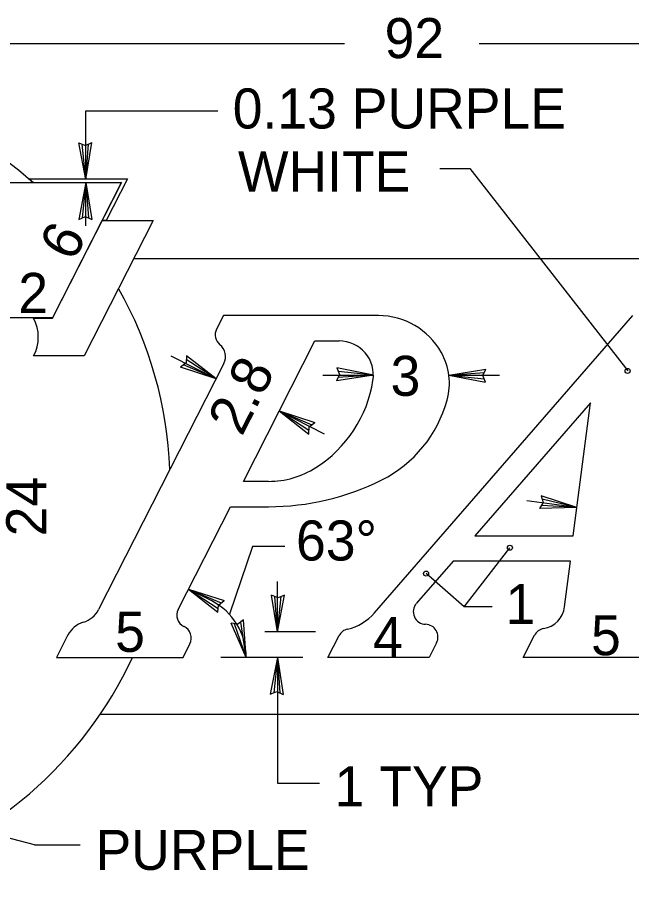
# Model space of a CAD drawing. Extents: x 10268197 to 10269179, y 2141503 to 2142677.
# Drawn here: x 10268485.36 to 10268496.1, y 2142121.42 to 2142136.69 of the extents above; entities that cross this region are included whole.
import ezdxf

# ---------------------------------------------------------------- set-up
doc = ezdxf.new("R2010")
doc.units = 0
for name, color, linetype in [('1', 7, 'Continuous'), ('3', 7, 'Continuous'), ('52', 7, 'Continuous'), ('SOILS_SP83_SHP', 7, 'Continuous')]:
    doc.layers.add(name, color=color, linetype=linetype)

msp = doc.modelspace()

# ---------------------------------------------------------------- linework, layer by layer
at = {"layer": '1'}
for p, q in [((10268467.878, 2142136.24), (10268491.08, 2142136.24)), ((10268493.435, 2142136.24), (10268512.635, 2142136.24)), ((10268486.559, 2142135.062), (10268488.866, 2142135.062)), ((10268486.559, 2142133.891), (10268486.559, 2142135.062)), ((10268492.748, 2142134.055), (10268493.275, 2142134.055)), ((10268493.275, 2142134.055), (10268496.035, 2142130.516)), ((10268486.559, 2142133.049), (10268486.559, 2142133.812)), ((10268485.973, 2142131.438), (10268486.842, 2142133.143)), ((10268487.736, 2142133.143), (10268486.53, 2142130.777)), ((10268486.842, 2142133.143), (10268487.736, 2142133.143)), ((10268485.644, 2142131.438), (10268485.973, 2142131.438)), ((10268486.53, 2142130.777), (10268485.645, 2142130.777)), ((10268488.047, 2142130.78), (10268488.835, 2142130.378)), ((10268490.703, 2142130.444), (10268491.588, 2142130.444)), ((10268492.906, 2142130.444), (10268493.791, 2142130.444)), ((10268489.94, 2142129.816), (10268490.728, 2142129.414)), ((10268495.146, 2142128.128), (10268494.269, 2142128.243)), ((10268489.47, 2142127.445), (10268489.069, 2142126.262)), ((10268490.039, 2142127.445), (10268489.47, 2142127.445)), ((10268493.177, 2142126.394), (10268493.974, 2142127.426)), ((10268493.177, 2142126.394), (10268492.508, 2142126.973)), ((10268489.908, 2142125.953), (10268489.908, 2142126.837)), ((10268488.76, 2142126.496), (10268488.353, 2142126.703)), ((10268493.666, 2142126.394), (10268493.177, 2142126.394)), ((10268490.572, 2142125.953), (10268489.687, 2142125.953)), ((10268490.351, 2142125.51), (10268488.921, 2142125.51)), ((10268489.908, 2142125.51), (10268489.908, 2142123.311)), ((10268489.908, 2142123.311), (10268490.645, 2142123.311)), ((10268485.66, 2142122.233), (10268483.388, 2142122.827)), ((10268485.66, 2142122.233), (10268486.461, 2142122.233))]:
    msp.add_line(p, q, dxfattribs=at)
for centre in [(10268496.034, 2142130.515), (10268493.974, 2142127.425), (10268492.508, 2142126.973)]:
    msp.add_circle(centre, 0.0442, dxfattribs=at)
for centre, radius, start, end in [((10268485.019, 2142131.107), 0.708, 332.2089, 27.9127), ((10268488.257, 2142125.51), 1.106, 0, 62.9941)]:
    msp.add_arc(centre, radius, start, end, dxfattribs=at)
at = {"layer": '3'}
msp.add_lwpolyline([(10268485.563, 2142133.872), (10268487.288, 2142133.872), (10268486.916, 2142133.143), (10268486.842, 2142133.143), (10268487.18, 2142133.806), (10268485.64, 2142133.805)], close=True, dxfattribs=at)
at = {"layer": '52'}
for p, q in [((10268486.56, 2142133.86), (10268486.436, 2142134.503)), ((10268486.436, 2142134.503), (10268486.55, 2142134.456)), ((10268486.56, 2142133.86), (10268486.496, 2142134.479)), ((10268486.55, 2142134.456), (10268486.663, 2142134.507)), ((10268486.56, 2142133.86), (10268486.663, 2142134.507)), ((10268486.56, 2142133.86), (10268486.604, 2142134.48)), ((10268486.56, 2142133.808), (10268486.436, 2142133.164)), ((10268486.56, 2142133.808), (10268486.496, 2142133.189)), ((10268486.56, 2142133.808), (10268486.663, 2142133.161)), ((10268486.56, 2142133.808), (10268486.604, 2142133.188)), ((10268486.436, 2142133.164), (10268486.55, 2142133.212)), ((10268486.55, 2142133.212), (10268486.663, 2142133.161)), ((10268488.32, 2142130.781), (10268488.31, 2142130.658)), ((10268488.835, 2142130.378), (10268488.314, 2142130.716)), ((10268488.835, 2142130.378), (10268488.32, 2142130.781)), ((10268488.31, 2142130.658), (10268488.213, 2142130.58)), ((10268488.835, 2142130.378), (10268488.213, 2142130.58)), ((10268488.835, 2142130.378), (10268488.264, 2142130.621)), ((10268491.588, 2142130.444), (10268490.945, 2142130.568)), ((10268490.945, 2142130.568), (10268490.992, 2142130.454)), ((10268492.906, 2142130.444), (10268493.553, 2142130.546)), ((10268493.502, 2142130.433), (10268493.553, 2142130.546)), ((10268490.992, 2142130.454), (10268490.941, 2142130.341)), ((10268491.588, 2142130.444), (10268490.941, 2142130.341)), ((10268491.588, 2142130.444), (10268490.968, 2142130.4)), ((10268491.588, 2142130.444), (10268490.969, 2142130.508)), ((10268492.906, 2142130.444), (10268493.525, 2142130.487)), ((10268492.906, 2142130.444), (10268493.549, 2142130.319)), ((10268492.906, 2142130.444), (10268493.524, 2142130.379)), ((10268493.549, 2142130.319), (10268493.502, 2142130.433)), ((10268489.94, 2142129.816), (10268490.563, 2142129.614)), ((10268489.94, 2142129.816), (10268490.456, 2142129.413)), ((10268489.94, 2142129.816), (10268490.461, 2142129.478)), ((10268489.94, 2142129.816), (10268490.512, 2142129.574)), ((10268490.456, 2142129.413), (10268490.466, 2142129.536)), ((10268490.466, 2142129.536), (10268490.563, 2142129.614)), ((10268495.146, 2142128.128), (10268494.524, 2142128.335)), ((10268494.524, 2142128.335), (10268494.557, 2142128.215)), ((10268495.146, 2142128.128), (10268494.541, 2142128.272)), ((10268494.557, 2142128.215), (10268494.491, 2142128.11)), ((10268495.146, 2142128.128), (10268494.491, 2142128.11)), ((10268495.146, 2142128.128), (10268494.526, 2142128.165)), ((10268488.353, 2142126.703), (10268488.976, 2142126.501)), ((10268488.353, 2142126.703), (10268488.869, 2142126.3)), ((10268488.353, 2142126.703), (10268488.874, 2142126.365)), ((10268488.353, 2142126.703), (10268488.925, 2142126.46)), ((10268489.908, 2142125.953), (10268489.806, 2142126.599)), ((10268489.919, 2142126.548), (10268489.806, 2142126.599)), ((10268489.908, 2142125.953), (10268489.865, 2142126.572)), ((10268489.908, 2142125.953), (10268490.033, 2142126.596)), ((10268489.908, 2142125.953), (10268489.973, 2142126.571)), ((10268490.033, 2142126.596), (10268489.919, 2142126.548)), ((10268488.869, 2142126.3), (10268488.878, 2142126.423)), ((10268488.878, 2142126.423), (10268488.976, 2142126.501)), ((10268489.364, 2142125.51), (10268489.097, 2142126.109)), ((10268489.219, 2142126.089), (10268489.097, 2142126.109)), ((10268489.318, 2142126.164), (10268489.219, 2142126.089)), ((10268489.364, 2142125.51), (10268489.266, 2142126.124)), ((10268489.364, 2142125.51), (10268489.318, 2142126.164)), ((10268489.364, 2142125.51), (10268489.161, 2142126.097)), ((10268489.908, 2142125.51), (10268489.783, 2142124.867)), ((10268489.908, 2142125.51), (10268489.844, 2142124.892)), ((10268489.908, 2142125.51), (10268490.011, 2142124.863)), ((10268489.908, 2142125.51), (10268489.952, 2142124.891)), ((10268489.783, 2142124.867), (10268489.898, 2142124.915)), ((10268489.898, 2142124.915), (10268490.011, 2142124.863))]:
    msp.add_line(p, q, dxfattribs=at)
at = {"layer": 'SOILS_SP83_SHP'}
for p, q in [((10268479.658, 2142133.806), (10268487.18, 2142133.806)), ((10268485.563, 2142133.872), (10268487.288, 2142133.872)), ((10268487.18, 2142133.806), (10268485.975, 2142131.441)), ((10268487.288, 2142133.872), (10268486.916, 2142133.143)), ((10268485.973, 2142131.438), (10268486.842, 2142133.143)), ((10268487.736, 2142133.143), (10268486.53, 2142130.777)), ((10268486.842, 2142133.143), (10268487.736, 2142133.143)), ((10268487.397, 2142132.479), (10268512.635, 2142132.479)), ((10268488.965, 2142131.483), (10268488.845, 2142131.247)), ((10268491.675, 2142131.483), (10268488.965, 2142131.483)), ((10268491.607, 2142126.287), (10268496.125, 2142131.483)), ((10268485.975, 2142131.441), (10268485.09, 2142131.441)), ((10268485.644, 2142131.438), (10268485.973, 2142131.438)), ((10268489.313, 2142128.585), (10268490.564, 2142131.041)), ((10268490.564, 2142131.041), (10268490.991, 2142131.041)), ((10268486.53, 2142130.777), (10268485.645, 2142130.777)), ((10268488.973, 2142130.647), (10268486.782, 2142126.348)), ((10268495.384, 2142129.957), (10268493.364, 2142127.634)), ((10268495.082, 2142127.634), (10268495.384, 2142129.957)), ((10268489.751, 2142128.585), (10268489.313, 2142128.585)), ((10268488.172, 2142126.348), (10268489.087, 2142128.143)), ((10268489.087, 2142128.143), (10268489.751, 2142128.143)), ((10268493.364, 2142127.634), (10268495.082, 2142127.634)), ((10268492.981, 2142127.191), (10268492.339, 2142126.454)), ((10268495.037, 2142127.191), (10268492.981, 2142127.191)), ((10268494.932, 2142126.392), (10268495.037, 2142127.191)), ((10268486.245, 2142125.901), (10268486.046, 2142125.51)), ((10268490.793, 2142125.51), (10268490.986, 2142125.889)), ((10268494.207, 2142125.51), (10268494.403, 2142125.895)), ((10268488.258, 2142125.51), (10268488.378, 2142125.747)), ((10268492.693, 2142125.766), (10268492.563, 2142125.51)), ((10268486.046, 2142125.51), (10268488.258, 2142125.51)), ((10268492.563, 2142125.51), (10268490.793, 2142125.51)), ((10268496.419, 2142125.51), (10268494.207, 2142125.51)), ((10268486.81, 2142124.515), (10268508.578, 2142124.515))]:
    msp.add_line(p, q, dxfattribs=at)
for centre, radius, start, end in [((10268480.957, 2142128.496), 7.079, 48.5904, 217.4727), ((10268480.957, 2142128.496), 7.079, 2.4236, 29.2771), ((10268491.675, 2142130.222), 1.261, 29.4315, 90), ((10268485.019, 2142131.107), 0.708, 332.2089, 27.9127), ((10268489.042, 2142131.146), 0.221, 152.9784, 231.1602), ((10268490.99, 2142130.443), 0.597, 351.076, 90), ((10268488.736, 2142130.767), 0.265, 333.0027, 51.1602), ((10268491.81, 2142130.298), 1.106, 344.7074, 29.4315), ((10268489.395, 2142130.693), 2.212, 302.4206, 351.076), ((10268490.743, 2142130.589), 2.212, 296.6431, 344.7074), ((10268489.751, 2142130.133), 1.548, 270, 302.4206), ((10268489.751, 2142132.567), 4.424, 270, 296.6431), ((10268492.506, 2142126.308), 0.221, 138.9824, 268.6869), ((10268486.388, 2142126.548), 0.442, 286.4317, 332.9959), ((10268488.369, 2142126.247), 0.221, 152.9884, 244.7832), ((10268490.939, 2142126.867), 0.885, 282.7162, 318.9966), ((10268494.493, 2142126.448), 0.442, 279.2397, 352.5632), ((10268486.639, 2142125.699), 0.442, 106.4317, 152.9742), ((10268488.181, 2142125.847), 0.221, 333.0239, 64.7832), ((10268491.183, 2142125.788), 0.221, 102.7162, 153.0239), ((10268492.496, 2142125.866), 0.221, 332.9784, 88.6869), ((10268494.6, 2142125.793), 0.221, 99.2397, 153.0239), ((10268480.957, 2142128.496), 7.079, 237.5383, 335.047)]:
    msp.add_arc(centre, radius, start, end, dxfattribs=at)

# ---------------------------------------------------------------- texts
at = {"layer": '1'}
for s, p in [('92', (10268491.783, 2142135.982)), ('0.13 PURPLE', (10268489.127, 2142134.752)), ('WHITE', (10268489.219, 2142133.651)), ('2', (10268485.377, 2142131.529)), ('3', (10268491.888, 2142130.08)), ('63°', (10268490.234, 2142127.202)), ('1', (10268493.897, 2142126.09)), ('5', (10268487.071, 2142125.606)), ('4', (10268491.58, 2142125.516)), ('5', (10268495.394, 2142125.547)), ('1 TYP', (10268490.91, 2142122.904)), ('PURPLE', (10268486.728, 2142121.795))]:
    msp.add_text(s, height=0.7, dxfattribs=at).set_placement(p)
for s, rotation, p in [('6', 63, (10268486.343, 2142132.404)), ('2.8', 62.9907, (10268489.286, 2142129.357)), ('24', 90, (10268485.866, 2142127.625))]:
    msp.add_text(s, height=0.7, rotation=rotation, dxfattribs=at).set_placement(p)

doc.saveas('drawing.dxf')
